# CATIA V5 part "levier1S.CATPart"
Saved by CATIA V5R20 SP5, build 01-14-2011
Part number: levier1S
Publications: "Droite.1", "Point.1", "Plan.1", "Point.5", "Point.6"
Bounding box of the stored display mesh (mm): x 0 to 0, y -90 to 200, z 1000 to 1350
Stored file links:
  U:\think motion\fin\levier1S.CATPart
  U:\think motion\fin\squelette.CATProduct
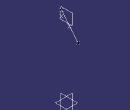
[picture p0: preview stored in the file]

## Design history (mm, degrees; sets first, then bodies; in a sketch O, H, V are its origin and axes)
External parameters (linked from other documents)
  `External.X colonne` = 200 mm
  `External.Y colonne` = 1000 mm
Set1
  Plane1: linked copy from another document
  Point1: linked copy from another document
  Point2: linked copy from another document
Set2
  Point3: type OnPlane, Support Plane1, H 200 {= `External.X colonne`}, V 1000 {= `External.Y colonne`}, Direction (0, 1, 0)
  Line1: type PtPt, FirstPoint Point1, SecondPoint Point3
  Point4: type Between, FirstPoint Point1, SecondPoint Point3, Ratio 0.5
Body1 (main body)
